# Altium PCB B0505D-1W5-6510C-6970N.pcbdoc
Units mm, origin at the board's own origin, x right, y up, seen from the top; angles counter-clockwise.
Board outline 33 x 16 mm, 2 copper layers (Top Layer, Bottom Layer), stack 0.78 mm thick; 15 components, 10 nets, 38 pads, 11 vias.
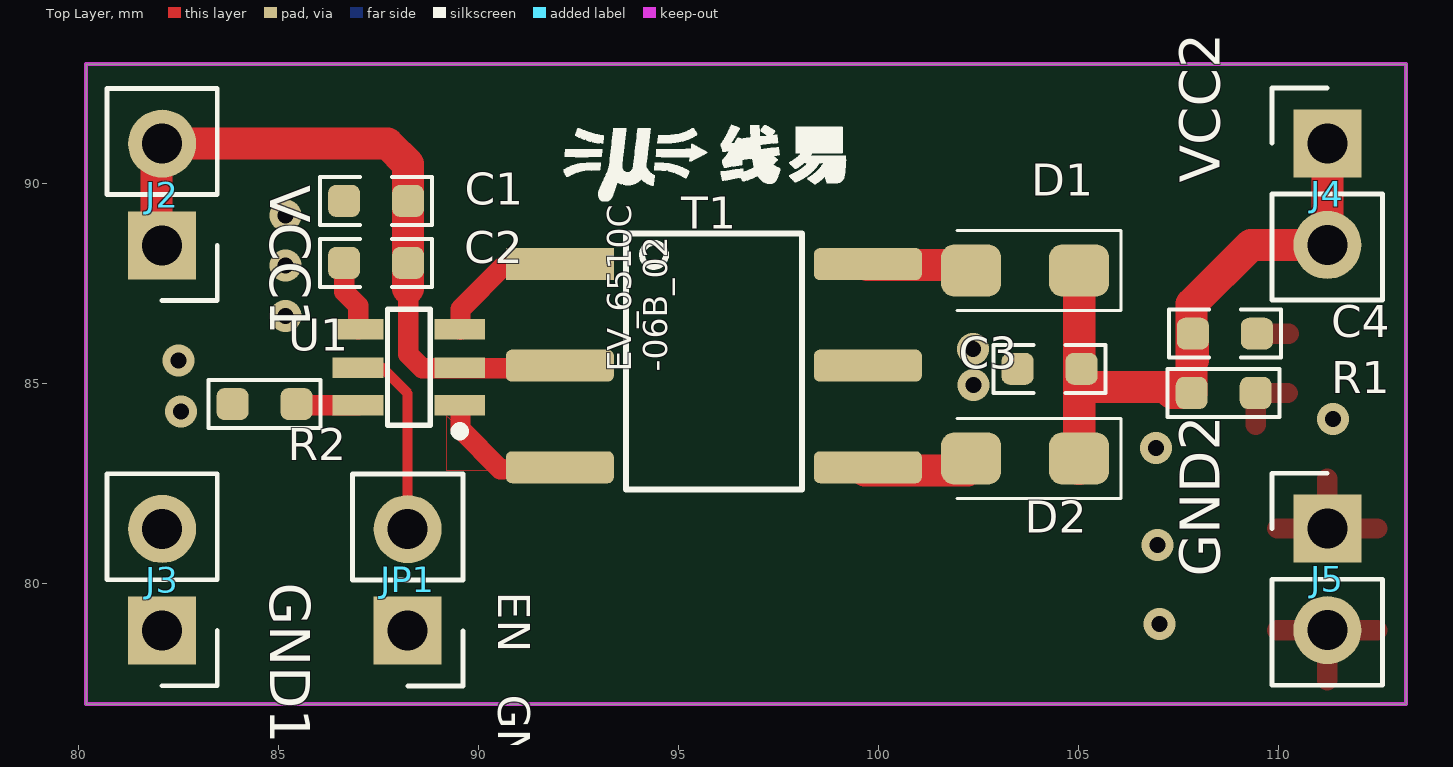
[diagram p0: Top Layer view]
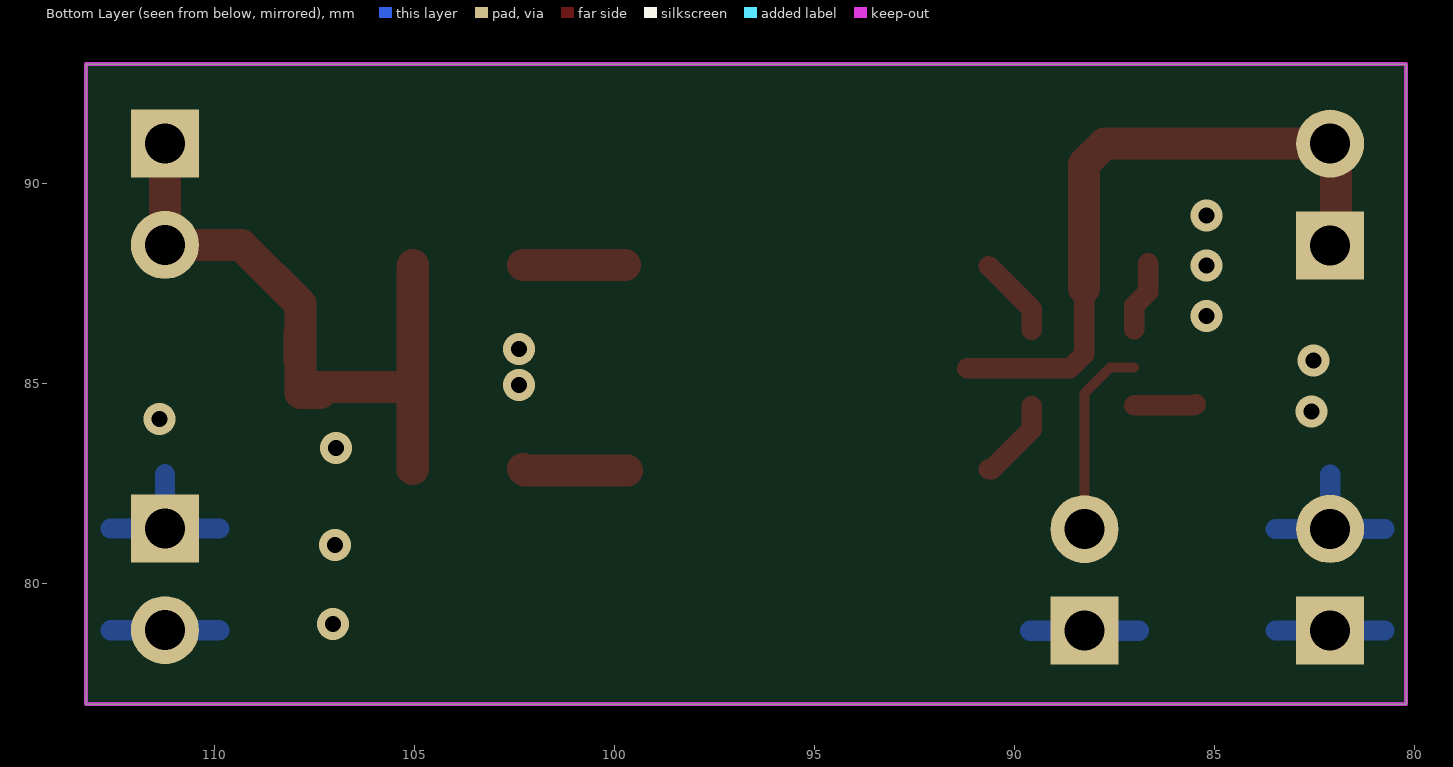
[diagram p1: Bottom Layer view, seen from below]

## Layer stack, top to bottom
Top Solder Mask Layer: solder mask 0.01, Dk 0
Top Layer: signal copper 0.035
dielectric 1: surface 0.71, FR4, Dk 4.5
Bottom Layer: signal copper 0.035
Bottom Solder Mask Layer: solder mask 0.01, Dk 0

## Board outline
80.2,92.99 113.2,92.99 113.2,76.99 80.2,76.99

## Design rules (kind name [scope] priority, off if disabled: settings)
BoardOutlineClearance copperThickness1oz [All] p0: genericclearance=0.254 ignorepadtopadclearanceinfootprint=FALSE except(0: Arc-SplitContinuation Track-SplitContinuation SMDPad-SplitContinuation THPad-SplitContinuation Via-SplitContinuation Fill-SplitContinuation Poly-SplitContinuation Region-SplitContinuation Text-SplitContinuation)
BoardOutlineClearance otherClearance [All] p0: genericclearance=0.254 ignorepadtopadclearanceinfootprint=FALSE except(0: Arc-SplitContinuation Track-SplitContinuation SMDPad-SplitContinuation THPad-SplitContinuation Via-SplitContinuation Fill-SplitContinuation Poly-SplitContinuation Region-SplitContinuation Text-SplitContinuation)
Clearance copperThickness1oz [All] p1: gap=0.178 ignorepadtopadclearanceinfootprint=FALSE
Clearance otherClearance [All] p1: gap=0.178 ignorepadtopadclearanceinfootprint=FALSE
DiffPairsRouting differentialPair [All] p1: maxuncoupledlength=10 minlimit=5 maxlimit=Infinity mostfreqgap=6 toplayer_minwidth=5 toplayer_prefwidth=100 toplayer_maxwidth=100 bottomlayer_minwidth=5 bottomlayer_prefwidth=100 bottomlayer_maxwidth=100
PasteMaskExpansion pasteMaskExpansion [All] p1: expansion=0
PlaneConnect innerPlane [All] p1: planeconnectstyle=Relief reliefexpansion=0.508 reliefentries=4 reliefconductorwidth=0.254 reliefairgap=0.254
PolygonConnect copper0 [All] p1: connectstyle=Direct reliefentries=4 reliefconductorwidth=10 polygonreliefangle="90 Angle" airgapwidth=10
PolygonConnect copper1 [All] p1: connectstyle=Relief reliefentries=4 reliefconductorwidth=20 polygonreliefangle="90 Angle" airgapwidth=15.748
PolygonConnect copper2 [All] p1: connectstyle=Relief reliefentries=4 reliefconductorwidth=20 polygonreliefangle="90 Angle" airgapwidth=20
RoutingVias viaSize [All] p1: viastyle="Through Hole" holewidth=24 minholewidth=11.811 maxholewidth=393.7 width=24 minwidth=11.811 maxwidth=393.7
SolderMaskExpansion solderMaskExpansion [All] p1: useseparateexpansions=TRUE expansion=2 expansionbottom=2
Width copperThickness1oz [All] p1: maxlimit=100 minlimit=5 preferedwidth=10

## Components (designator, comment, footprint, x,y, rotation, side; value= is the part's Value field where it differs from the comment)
C1 "10uF" C0603 87.45,89.57 r0 top
C2 "100nF" C0603 87.45,88.02 r0 top
C3 "10uF" C0603 104.288,85.374 r0 top
C4 "100nF" C0603 108.67,86.25 r180 top
D1 "B5819W" SOD-123_L2.7-W1.6-LS3.7-FD 103.674,87.83 r180 top
D2 "B5819W" SOD-123_L2.7-W1.6-LS3.7-FD 103.674,83.13 r180 top
J2 "HX PZ2.54-1x2P ZZ" HDR-TH_2P-P2.54-V-M-3 82.1,88.46 r180 top
J3 "HX PZ2.54-1x2P ZZ" HDR-TH_2P-P2.54-V-M-3 82.1,78.83 r180 top
J4 "HX PZ2.54-1x2P ZZ" HDR-TH_2P-P2.54-V-M-3 111.23,91.01 r0 top
J5 "Connector_Generic_Conn_01x02" Connector_PinHeader_2.54mm:PinHeader_1x02_P2.54mm_Vertical 111.23,81.38 r0 top
JP1 "Jumper_Jumper_2_Open" Connector_PinHeader_2.54mm:PinHeader_1x02_P2.54mm_Vertical 88.24,78.825 r180 top
R1 "4.7kΩ" R0603 108.64,84.77 r0 top
R2 "My_Library_R" MYLibrary:R0603 84.66,84.49 r180 top
T1 "" ? 95.895,85.451 r0 top
U1 "MYLibrary _CMP6510C" MYLibrary:SOT23-6 88.27,85.4 r180 top

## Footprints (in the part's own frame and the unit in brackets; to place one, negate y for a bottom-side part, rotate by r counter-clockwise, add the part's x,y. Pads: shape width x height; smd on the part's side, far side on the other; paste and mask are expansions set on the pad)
C0603 [mm]
  rrect50% 0.8x0.8 smd: 1(-0.8,0) 2(0.8,0)
  silkscreen extent -1.4,-0.6 1.4,0.6
Connector_PinHeader_2.54mm:PinHeader_1x02_P2.54mm_Vertical [mm]
  rect 1.7x1.7 hole 1: 1(0,0)
  round 1.7 hole 1: 2(0,-2.54)
  silkscreen extent -1.38,-3.92 1.38,1.38
HDR-TH_2P-P2.54-V-M-3 [mm]
  rect 1.7x1.7 hole 1: 1(0,0)
  round 1.7 hole 1: 2(0,-2.54)
  silkscreen extent -1.38,-3.92 1.38,1.38
MYLibrary:R0603 [mm]
  rrect50% 0.8x0.8 smd: 1(-0.8,0) 2(0.8,0)
  silkscreen extent -1.4,-0.6 1.4,0.6
MYLibrary:SOT23-6 [mil]
  rect 50x20 smd: 1(-50,37) 2(-50,0) 3(-50,-38) 4(50,-38) 5(50,0) 6(50,37)
  silkscreen extent -54,-58 21,66
R0603 [mm]
  rrect50% 0.8x0.8 smd: 1(-0.8,0) 2(0.8,0)
  silkscreen extent -1.4,-0.6 1.4,0.6
SOD-123_L2.7-W1.6-LS3.7-FD [mm]
  rrect50% 1.5x1.3 smd: 1(-1.35,0) 2(1.35,0)
  silkscreen extent -2.4,-1 1.7,1
? [mm]
  rect 2.7x0.8 smd: 1(-3.85,2.54)
  rrect37% 2.7x0.8 smd: 2(-3.85,0) 3(-3.85,-2.54) 4(3.85,-2.54) 5(3.85,0) 6(3.85,2.54)
  silkscreen extent -2.2,-3.1 2.2,3.3

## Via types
v1: diameter 0.8, hole 0.4, Top Layer to Bottom Layer, 11 vias

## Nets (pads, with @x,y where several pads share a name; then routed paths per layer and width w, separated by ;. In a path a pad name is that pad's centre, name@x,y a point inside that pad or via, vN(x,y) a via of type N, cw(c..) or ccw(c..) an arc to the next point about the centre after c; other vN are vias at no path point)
$1N6: D2.2 T1.4 | length 2.6
  Top Layer w0.8: T1.4@99.672,82.83 102.234,82.83 D2.2@102.274,82.87
$1N9: D1.2 T1.6 | length 2.5
  Top Layer w0.8: T1.6@99.732,87.97 D1.2@102.274,87.97
$1N15: T1.1 U1.3 | length 2
  Top Layer w0.508: U1.3@89.56,86.344 89.56,86.868 90.636,87.944
$1N16: T1.3 U1.1 | length 2.1
  Top Layer w0.508: U1.1@89.56,84.439 89.56,83.86 90.556,82.864 90.636,82.864
CLK: R2.1 U1.6 | length 1.6
  Top Layer w0.508: R2.1 85.49,84.46 U1.6
EN: JP1.2 U1.5 | length 4.9
  Top Layer w0.25: U1.5 87.601,85.4 88.24,84.761 JP1.2
GND1: C1.1 C2.1 J3.1 J3.2 JP1.1 R2.2 U1.4 | length 1.8
  Top Layer w0.508: C2.1 86.65,87.3 87,86.95 U1.4
  other v1: 82.57,84.31 82.51,85.58 85.19,86.69 85.19,87.95 85.19,89.21
GND2: C3.1 C4.1 J5.1 J5.2 R1.2 T1.5
  other v1: 107.03,78.99 106.98,80.97 106.95,83.39 111.37,84.12 102.383,84.97 102.374,85.87
VCC1: C1.2 C2.2 J2.1 J2.2 T1.2 U1.2 | length 16.6
  Top Layer w0.508: 88.25,87.38 88.25,85.74 88.601,85.389 T1.2@91.178,85.389
  Top Layer w0.8: J2.1@81.955,88.69 81.955,90.855 J2.2 87.74,91 88.25,90.49 C1.2 C2.2 88.25,87.38
VCC2: C3.2 C4.2 D1.1 D2.1 J4.1 J4.2 R1.1 | length 23.2
  Top Layer w0.6: D2.1@105.14,82.834 105.14,84.92 D1.1@105.14,87.914
  Top Layer w0.8: D2.1@105.024,82.87 D1.1@105.024,87.97 ; 105.088,84.92 105.14,84.92 107.2,84.92 ; 107.84,85.56 107.87,85.59 C4.2 ; J4.1 J4.2 109.32,88.47 107.84,86.99 R1.1 ; 107.2,84.92 107.35,84.77 R1.1 ; 107.2,84.92 107.69,84.92 R1.1

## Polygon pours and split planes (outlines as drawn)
GND1 on Top Layer (solid, remove dead copper, pour order 2): 87.105,89.835 87.105,82.835 89.2,82.835 89.2,77.01 76.32,77.01 76.32,84.81 78.62,84.81 80.72,86.91 80.72,89.835
GND1 on Top Layer (solid, remove dead copper, pour order 2): 89.2,82.835 90.74,82.835 89.2,84.201
GND1 on Bottom Layer (solid, remove dead copper, pour order 12): 91.9,76.99 76.2,76.99 76.2,92.99 91.9,92.99
GND2 on Top Layer (solid, remove dead copper, pour order 6): 103.888,84.474 102.024,84.474 102.024,84.47 101.738,84.774 99.238,84.774 99.188,85.974 101.688,85.974 101.924,86.37 101.924,86.374 103.888,86.374
GND2 on Top Layer (solid, remove dead copper, pour order 8): 113.324,76.906 106.27,76.956 106.3,76.96 106.279,80.64 106.279,84.036 108.754,84.036 108.954,84.336 108.954,86.866 113.324,86.866
GND2 on Bottom Layer (solid, remove dead copper, pour order 18): 113.225,77.006 96.975,77.058 96.975,93.058 113.225,93.006

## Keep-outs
Board Outline Layer:
  the board outline again, w0.1

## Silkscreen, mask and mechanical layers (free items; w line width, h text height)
Top Silkscreen Layer:
  drawing of 9 lines, arcs and shapes, not listed
  text "VCC2" at 108.54,90.03 h1 r90
  text "VCC1" at 84.8,89.96 h1 r270
  text "EV_6510C / -06B_02" at 94.73,85.304 h0.6 r90
  text "GND2" at 108.54,80.17 h1 r90
  text "GND1" at 84.8,80.03 h1 r270
  text "EN   GND1" at 90.5,79.8 h0.8 r270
